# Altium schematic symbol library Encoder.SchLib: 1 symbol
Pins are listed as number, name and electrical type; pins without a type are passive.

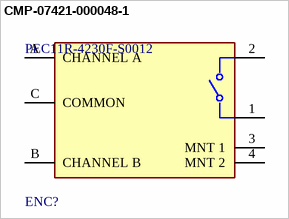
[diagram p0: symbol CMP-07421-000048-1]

## CMP-07421-000048-1
designator ENC?, comment PEC11R-4230F-S0012
ROTARY ENCODER MECHANICAL 12PPR; Detent: Yes; Hole Diameter: 1.8mm; Number of Channels: 2; Pulses per Revolution: 12; Output Type: Quadrature
footprint FP-PEC11R-4230F-S0012-MFG
pins: 1, 2, 3 MNT 1, 4 MNT 2, A CHANNEL A, B CHANNEL B, C COMMON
